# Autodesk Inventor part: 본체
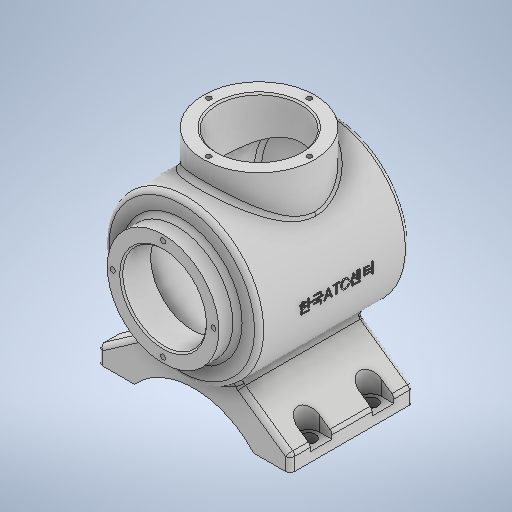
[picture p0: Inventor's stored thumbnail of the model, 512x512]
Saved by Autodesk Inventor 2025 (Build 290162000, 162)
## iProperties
Created: 2024-07
Part Number: 본체
Material: 일반
Document SubType Name: Modeling
Designer: admin
Density: 1 g/cm^3
Appearance: 기본값
Author: admin
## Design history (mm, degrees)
sketch "스케치3"
  geometry: L1 (0, 54)-(-50, 54); L2 (-50, 54)-(-50, -42.336); L3 (0, -54)-(0, 54); A1 r 113 centre (0, 59) between (-50, -42.336) and (50, -42.336); 3 further points
  constraints: 6 end point, 4 point on circle, 2 midpoint, 1 centre point, 1 coincident, 1 horizontal, 1 horizontal alignment, 1 parallel, 1 perpendicular, 1 vertical alignment
  dimensions: "d3" = 50 distance of L1.start L1.end; "d10" = 113 radius of A1; "d11" = 108 distance from line of L3.start L1
revolve "회전1" sketch "스케치3" stored, may be unused: angle "d8" = 90 deg
fillet "모깎기1" dims "d12" = 3
feature "쉘1" dims "d13" = 7
sketch "스케치4"
  geometry: C1 r 36 at (0, 0); 1 further point
  constraints: 1 centre point, 1 coincident
  dimensions: "d14" = 72 diameter of C1
extrude "돌출2" join sketch "스케치4" distance "d15" = 12; taper "d16" = 0 deg
sketch "스케치5"
  geometry: C1 r 36 at (0, 0) reference; 2 further points
  constraints: 1 coincident
hole "구멍1" sketch "스케치5" at (0, 0) diameter "d17" = 54; stored, may be unused: countersink angle "d21" = 90 deg, drill point angle "d23" = 0 deg; dims "d18" = 8, "d19" = 4, "d20" = 2, "d22" = 19
sketch "스케치7"
  geometry: L1 (0, 46.396)-(0, -104.361); L2 (-62, -77)-(62, -77); L3 (62, -77)-(62, -67); L4 (62, -67)-(24.427, -40.691); L5 (-24.427, -40.691)-(-62, -67); L6 (-62, -67)-(-62, -77); A1 r 48.181 centre (0, 0.839) between (-24.427, -40.691) and (24.427, -40.691); 1 further point
  constraints: 12 end point, 2 point on circle, 1 centre point, 1 horizontal, 1 horizontal alignment, 1 parallel, 1 perpendicular, 1 point on line, 1 vertical, 2 other
  dimensions: "d32" = 55 deg angle of L6 L5; "d33" = 10 distance of L5.end L2.start; "d34" = 77 distance from line of point (0, 0) L2; "d36" = 124 distance of L2.start L2.end; "d37" = 48.18065 radius of A1; "d38" = 45.86871 distance of L5.start L5.end
extrude "돌출3" join sketch "스케치7" distance "d39" = 46; taper "d40" = 0 deg; dims "d131" = 34, "d132" = 0
node "작업 평면2"
sketch "스케치9"
  geometry: L1 (-26, 100)-(-98, 100) reference; C1 r 36 at (-62, 38); 2 further points
  constraints: 1 centre point, 1 coincident, 1 midpoint, 1 vertical alignment
  dimensions: "d46" = 72 diameter of C1; "d118" = 62 distance from line of point (-62, 38) L1
extrude "돌출5" join sketch "스케치9" stored distance "d47" = 10; taper "d48" = 0 deg
sketch "스케치10"
  geometry: C1 r 36 at (0, 0) reference; 2 further points
  constraints: 1 coincident
hole "구멍2" sketch "스케치10" at (0, 0) diameter "d49" = 54; stored, may be unused: countersink angle "d53" = 90 deg, drill point angle "d55" = 0 deg; dims "d50" = 6, "d51" = 4, "d52" = 2, "d54" = 40
fillet "모깎기2" dims "d56" = 3
fillet "모깎기4" dims "d74" = 3
fillet "모깎기3" dims "d57" = 3
chamfer "모따기1" distance "d58" = 1; stored, may be unused: second distance "d59" = 2, angle "d60" = 45 deg
sketch "스케치11"
  geometry: L1 (-8, 67)-(0, 67); L2 (0, 0)-(0, 80) reference; L3 (-8, 53)-(0, 53); L4 (-124, 80)-(0, 80) reference; L5 (-135.9, 34)-(24.657, 34); L6 (-62, 72.718)-(-62, -22.908); L7 (-124, 0)-(-124, 80) reference; L8 (-8, 1)-(0, 1); L9 (-8, 15)-(0, 15); L10 (-116, 53)-(-124, 53); L11 (-116, 67)-(-124, 67); L12 (-116, 15)-(-124, 15); L13 (-116, 1)-(-124, 1); A1 r 7 centre (-8, 60) between (-8, 67) and (-8, 53); A2 r 7 centre (-8, 8) between (-8, 15) and (-8, 1); A3 r 7 centre (-116, 60) between (-116, 53) and (-116, 67); A4 r 7 centre (-116, 8) between (-116, 1) and (-116, 15); 9 further points
  constraints: 20 end point, 15 symmetric about line, 8 point on circle, 4 centre point, 4 point on line, 2 horizontal, 1 midpoint, 1 parallel, 1 tangent, 1 vertical, 3 other
  dimensions: "d61" = 14 diameter of A1; "d62" = 14 distance from line of point (-4, 53) L1; "d63" = 20 distance from line of A1.centre L4; "d64" = 8 distance from line of L2 A1.centre
sketch "스케치15" dims "d119" = 65
  geometry: L1 (50, 44.454)-(50, -47) reference; C1 r 36 at (0, 0) reference; 3 further points
  constraints: 2 horizontal alignment, 3 other
hole "구멍3" sketch "스케치15" at (-32.5, 0) diameter "d76" = 3.242; stored, may be unused: countersink angle "d80" = 90 deg, drill point angle "d82" = 118 deg; dims "d77" = 8, "d78" = 4, "d79" = 2, "d81" = 10
fillet "모깎기6" dims "d98" = 3
fillet "모깎기7" dims "d99" = 3
node "작업 평면4"
sketch "스케치19"
  geometry: L1 (36, 66)-(-36, 66) reference; 2 further points
  constraints: 1 vertical alignment, 1 other
  dimensions: "d115" = 62 distance from line of L1 point (0, 4)
feature "엠보싱1" sketch "스케치19" dims "d3" = 50, "d10" = 113, "d11" = 108, "d116" = 0.5, "d117" = 0
sketch "스케치20" dims "d120" = 65
  geometry: 3 further points
  constraints: 2 vertical alignment, 1 coincident, 2 other
hole "구멍7" sketch "스케치20" at (0, 32.5) diameter "d121" = 3.242; stored, may be unused: countersink angle "d125" = 90 deg, drill point angle "d127" = 118 deg; dims "d122" = 8, "d123" = 4, "d124" = 2, "d126" = 10
node "작업 평면5"
sketch "스케치22"
  geometry: L1 (124, -80)-(124, 0) reference; L2 (0, 0)-(124, 0) reference; L3 (116, -13)-(124, -13); L4 (122.721, -80)-(122.721, 0) reference; L5 (116, -27)-(124, -27); L6 (-20.578, -40)-(180.889, -40); L7 (62, 44.885)-(62, -136.998); L8 (116, -53)-(124, -53); L9 (116, -67)-(124, -67); L10 (8, -27)-(0, -27); L11 (8, -13)-(0, -13); L12 (8, -53)-(0, -53); L13 (8, -67)-(0, -67); L14 (0, -80)-(0, 0) reference; A1 r 7 centre (116, -20) between (116, -13) and (116, -27); A2 r 7 centre (116, -60) between (116, -53) and (116, -67); A3 r 7 centre (8, -20) between (8, -27) and (8, -13); A4 r 7 centre (8, -60) between (8, -67) and (8, -53); 3 further points
  constraints: 20 end point, 15 symmetric about line, 8 point on circle, 4 centre point, 2 horizontal, 2 perpendicular, 2 point on line, 2 vertical alignment, 1 tangent, 1 vertical, 3 other
  dimensions: "d134" = 14 diameter of A1; "d135" = 8 distance of L3.start L3.end; "d136" = 20 distance from line of L2 A1.centre; "d137" = 40 distance between parallel lines of L6 L2; "d138" = 62 distance between parallel lines of L1 L7
extrude "돌출9" cut sketch "스케치22" distance "d139" = 19.75; taper "d140" = 0 deg
sketch "스케치23"
  geometry: A1 r 7 centre (116, 20) between (116, 27) and (116, 13) reference; A2 r 7 centre (116, 60) between (116, 67) and (116, 53) reference; A3 r 7 centre (8, 20) between (8, 13) and (8, 27) reference; A4 r 7 centre (8, 60) between (8, 53) and (8, 67) reference; 5 further points
  constraints: 4 coincident
hole "구멍8" sketch "스케치23" at (116, 20), (116, 60), (8, 20), (8, 60) diameter "d141" = 9; stored, may be unused: countersink angle "d145" = 90 deg, drill point angle "d147" = 0 deg; dims "d142" = 6, "d143" = 4, "d144" = 2, "d146" = 19
sketch "스케치24"
  geometry: L1 (-62, -77)-(62, -77) reference; A1 r 52.096 centre (0, -112.096) between (38.5, -77) and (-38.5, -77); 2 further points
  constraints: 3 point on circle, 2 point on line, 1 centre point, 1 vertical alignment
  dimensions: "d148" = 77 distance of A1.start A1.end; "d149" = 17 distance from line of L1 point (0, -60)
extrude "돌출10" cut sketch "스케치24" extent not by distance; stored distance "d150" = 0; taper "d151" = 0 deg
fillet "모깎기8" dims "d152" = 3
node "솔리드2"
pattern_circular "원형 패턴1" dims angle "d84" = 360 deg
pattern_circular "원형 패턴3" dims angle "d129" = 360 deg
feature "A9D066F2-1C7D-4E18-AEED-F7BC21143FA4" dims "d17" = 54, "d18" = 8, "d19" = 4, "d20" = 2, "d21" = 90 deg, "d22" = 19, "d23" = 0
other parameters: "d45" = -142, "d114" = 119.75, "d133" = -25.75
